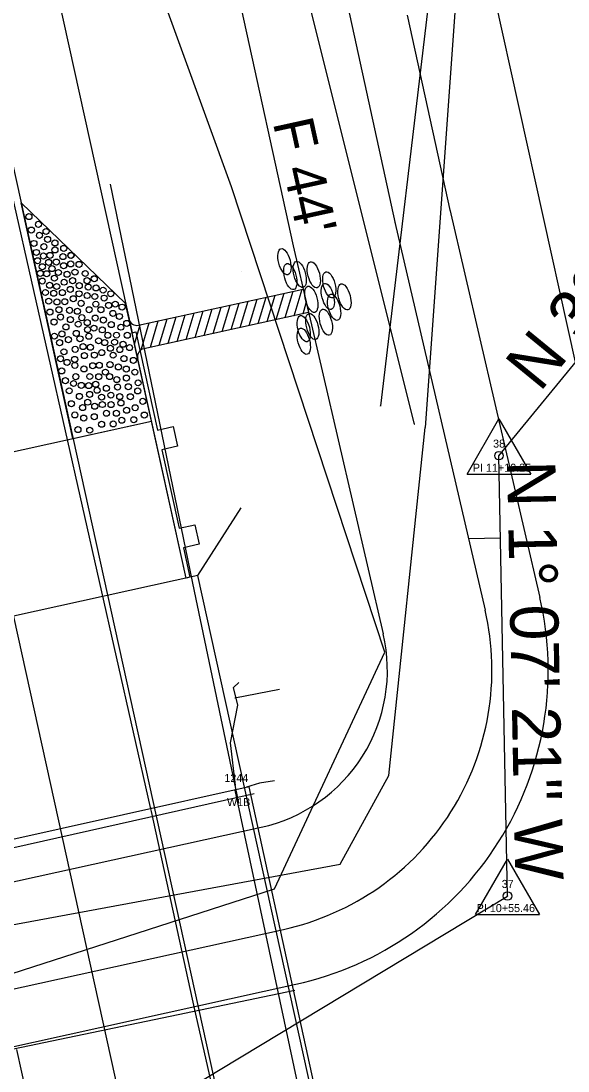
# Model space of a CAD drawing. Extents: x 2519952 to 2531965, y 848341 to 887632.
# Drawn here: x 2524474.1 to 2524542.1, y 869931.6 to 870062.2 of the extents above; entities that cross this region are included whole.
import ezdxf

# ---------------------------------------------------------------- set-up
doc = ezdxf.new("R2010")
doc.units = 0
for name, color, linetype in [('RD_EV_JW', 7, 'Continuous'), ('RD_EX_BldgApp', 7, 'Continuous'), ('RD_EX_BldgApp_txCode', 7, 'Continuous'), ('RD_EX_Bridge', 7, 'Continuous'), ('RD_EX_Conc', 7, 'Continuous'), ('RD_EX_DR_Pipe', 7, 'Continuous'), ('RD_EX_DV_Prop', 7, 'Continuous'), ('RD_EX_GuardRail', 7, 'Continuous'), ('RD_EX_H2O', 7, 'Continuous'), ('RD_EX_Misc', 7, 'Continuous'), ('RD_EX_Road', 7, 'Continuous'), ('RD_EX_RW', 7, 'Continuous'), ('RD_EX_VEG', 7, 'Continuous'), ('RD_HC_Cl', 7, 'Continuous'), ('RD_HC_Data', 7, 'Continuous'), ('RD_HC_Data_Tic', 7, 'Continuous'), ('RD_HC_txCode', 7, 'Continuous'), ('RD_PD_BCA', 7, 'Continuous'), ('RD_PD_Bridge', 7, 'Continuous'), ('RD_PD_CstnLmt', 7, 'Continuous'), ('RD_PD_DR_ErosCtrl', 7, 'Continuous'), ('RD_PD_Final_TrvlWay', 7, 'Continuous'), ('RD_PD_GR', 7, 'Continuous'), ('RD_PD_PaveShd', 7, 'Continuous'), ('RD_PD_TX_CstnLmt', 7, 'Continuous'), ('RD_SMD_Locator', 7, 'Continuous')]:
    doc.layers.add(name, color=color, linetype=linetype)

# ---------------------------------------------------------------- blocks, each defined once
blk = doc.blocks.new('TBC1')
at = {"layer": 'RD_PD_GR'}
blk.add_lwpolyline([(12.5, 2.5), (15, 2.5), (15, 0.49), (25, 0.49), (25, 2.5), (27.5, 2.5), (27.5, 0.49), (31.25, 0.49), (31.25, 0), (0, 0), (0, 0.49), (12.5, 0.49)], close=True, dxfattribs=at)

msp = doc.modelspace()

# ---------------------------------------------------------------- linework, layer by layer
at = {"layer": 'RD_EV_JW'}
msp.add_lwpolyline([(2524458.62, 869939.06), (2524505.66, 869954.24), (2524519.37, 869983.67), (2524500.31, 870041.58), (2524475.26, 870110.59), (2524445.65, 870249.35), (2524428.13, 870321.9), (2524406.09, 870422.33), (2524396.17, 870467.05), (2524425.28, 870470.84), (2524454.75, 870476.78)], dxfattribs=at)
at = {"layer": 'RD_EX_BldgApp'}
msp.add_lwpolyline([(2524516.89, 869892.47), (2524508.77, 869928.99), (2524500.76, 869966.53)], dxfattribs=at)
at = {"layer": 'RD_EX_Bridge'}
for points in [[(2524472.36, 869882.63), (2524518.65, 869892.86), (2524502.52, 869966.92), (2524455.6, 869956.47), (2524472.36, 869882.63)], [(2524505.65, 869967.69), (2524503.79, 869967.38), (2524502.16, 869966.89)]]:
    msp.add_lwpolyline(points, dxfattribs=at)
at = {"layer": 'RD_EX_Conc'}
msp.add_lwpolyline([(2524500.79, 869967.1), (2524500.19, 869972.39), (2524501.1, 869977.08), (2524500.57, 869979.27), (2524501.22, 869979.92)], dxfattribs=at)
at = {"layer": 'RD_EX_DR_Pipe'}
msp.add_line((2524500.72, 869978), (2524506.26, 869979.09), dxfattribs=at)
at = {"layer": 'RD_EX_DV_Prop'}
msp.add_line((2524527.61, 870089.75), (2524592.12, 869796.77), dxfattribs=at)
at = {"layer": 'RD_EX_GuardRail'}
msp.add_lwpolyline([(2524501.24, 869964.94), (2524495.69, 869991.29), (2524485.25, 870041.92)], dxfattribs=at)
at = {"layer": 'RD_EX_H2O'}
for points in [[(2524762.31, 869970.18), (2524733.82, 870018.81), (2524754.68, 870057.75), (2524729.41, 870096.66), (2524680.71, 870131.33), (2524638.06, 870116.86), (2524602.29, 870110.04), (2524572.44, 870077.13), (2524547.77, 870085.27), (2524528.12, 870063.83), (2524524.38, 870011.64)], [(2524436.36, 869952.53), (2524441.15, 869943.87), (2524513.81, 869957.32), (2524519.88, 869968.33), (2524524.38, 870011.64)]]:
    msp.add_lwpolyline(points, dxfattribs=at)
at = {"layer": 'RD_EX_Misc'}
for p, q in [((2524455.91, 869955.49), (2524503.11, 869966.09)), ((2524508.17, 869941.6), (2524461.28, 869931.83))]:
    msp.add_line(p, q, dxfattribs=at)
msp.add_lwpolyline([(2524763.76, 869970.38), (2524734.76, 870019.18), (2524755.4, 870058.09), (2524736.98, 870088.2), (2524730.38, 870097.59), (2524680.98, 870133.01), (2524637.69, 870118.3), (2524601.59, 870111.28), (2524572.31, 870077.7), (2524547.41, 870087.54), (2524525.11, 870066.96), (2524518.84, 870014.31)], dxfattribs=at)
at = {"layer": 'RD_EX_Road'}
for p, q in [((2524490.23, 869964.34), (2524468.69, 870059.82)), ((2524490.35, 869963.86), (2524490.23, 869964.34)), ((2524495.76, 869939.17), (2524490.35, 869963.86)), ((2524501.25, 869914.97), (2524495.76, 869939.17)), ((2524478.97, 869909.8), (2524473.63, 869934.24))]:
    msp.add_line(p, q, dxfattribs=at)
at = {"layer": 'RD_EX_RW'}
msp.add_line((2524527.61, 870089.75), (2524592.12, 869796.77), dxfattribs=at)
at = {"layer": 'RD_EX_VEG'}
msp.add_lwpolyline([(2524523.08, 870012.04), (2524509.32, 870067.13), (2524430.48, 870459.25), (2524384.56, 870681.27)], dxfattribs=at)
at = {"layer": 'RD_HC_Cl'}
for p, q in [((2524338.62, 870599.23), (2524895.21, 868071.59)), ((2524533.56, 870008.13), (2524581.12, 870066.26)), ((2524534.63, 869953.35), (2524533.56, 870008.13)), ((2524369.5, 869853.66), (2524534.63, 869953.35))]:
    msp.add_line(p, q, dxfattribs=at)
at = {"layer": 'RD_HC_Data'}
for p, q in [((2524529.59, 870005.84), (2524533.56, 870012.72)), ((2524533.56, 870012.72), (2524537.53, 870005.84)), ((2524529.59, 870005.84), (2524537.53, 870005.84)), ((2524530.66, 869951.06), (2524534.64, 869957.94)), ((2524534.64, 869957.94), (2524538.6, 869951.06)), ((2524530.66, 869951.06), (2524538.6, 869951.06))]:
    msp.add_line(p, q, dxfattribs=at)
for centre in [(2524533.56, 870008.13), (2524534.63, 869953.35)]:
    msp.add_circle(centre, 0.529, dxfattribs=at)
at = {"layer": 'RD_HC_Data_Tic'}
msp.add_line((2524533.76, 869997.87), (2524529.76, 869997.8), dxfattribs=at)
at = {"layer": 'RD_PD_BCA'}
for p, q in [((2524522.16, 870062.95), (2524527.5, 870038.5)), ((2524527.45, 870038.75), (2524538.66, 869990.48))]:
    msp.add_line(p, q, dxfattribs=at)
msp.add_lwpolyline([(2524459.51, 869931.62), (2524508.29, 869942.37)], dxfattribs=at)
msp.add_arc((2524499.69, 869981.43), 40, 282.4185, 13.0724, dxfattribs=at)
at = {"layer": 'RD_PD_Bridge'}
for p, q in [((2524447.39, 870002.97), (2524490.36, 870012.43)), ((2524494.66, 869992.9), (2524490.36, 870012.43)), ((2524496.13, 869993.22), (2524501.51, 870001.65))]:
    msp.add_line(p, q, dxfattribs=at)
for points in [[(2524496.13, 869993.22), (2524450.23, 869983.12)], [(2524524.08, 869866.26), (2524496.13, 869993.22)]]:
    msp.add_lwpolyline(points, dxfattribs=at)
at = {"layer": 'RD_PD_CstnLmt'}
for p, q in [((2524486.6, 870131.92), (2524507.97, 870034.23)), ((2524507.97, 870034.23), (2524519.17, 869985.96))]:
    msp.add_line(p, q, dxfattribs=at)
msp.add_lwpolyline([(2524455.21, 869951.16), (2524503.99, 869961.9)], dxfattribs=at)
msp.add_arc((2524499.69, 869981.43), 20, 282.4185, 13.0724, dxfattribs=at)
at = {"layer": 'RD_PD_DR_ErosCtrl'}
for p, q in [((2524499.3, 870134.69), (2524520.67, 870037)), ((2524520.63, 870037.17), (2524531.84, 869988.9))]:
    msp.add_line(p, q, dxfattribs=at)
msp.add_lwpolyline([(2524458, 869938.46), (2524506.79, 869949.2)], dxfattribs=at)
msp.add_arc((2524499.69, 869981.43), 33, 282.4185, 13.0724, dxfattribs=at)
at = {"layer": 'RD_PD_Final_TrvlWay'}
msp.add_line((2524439.2, 870198.28), (2524713.39, 868953.11), dxfattribs=at)
at = {"layer": 'RD_PD_GR'}
msp.add_line((2524439.56, 870243.16), (2524487.94, 870023.42), dxfattribs=at)
at = {"layer": 'RD_PD_PaveShd'}
for p, q in [((2524474.14, 870039.58), (2524487.14, 870027.08)), ((2524480.6, 870010.28), (2524474.14, 870039.58)), ((2524488.76, 870024.37), (2524509.21, 870028.86)), ((2524504.74, 870024.81), (2524505.73, 870028.09)), ((2524504.74, 870024.81), (2524505.73, 870028.09)), ((2524505.86, 870025.05), (2524506.84, 870028.34)), ((2524505.86, 870025.05), (2524506.84, 870028.34)), ((2524506.98, 870025.3), (2524507.96, 870028.58)), ((2524506.98, 870025.3), (2524507.84, 870028.18)), ((2524508.09, 870025.54), (2524509.08, 870028.83)), ((2524508.09, 870025.54), (2524509.08, 870028.83)), ((2524509.21, 870028.86), (2524509.89, 870025.94)), ((2524487.78, 870024.15), (2524487.14, 870027.08)), ((2524499.15, 870023.58), (2524500.14, 870026.87)), ((2524499.15, 870023.58), (2524500.14, 870026.87)), ((2524500.27, 870023.82), (2524501.26, 870027.11)), ((2524500.27, 870023.82), (2524501.26, 870027.11)), ((2524501.39, 870024.07), (2524502.37, 870027.36)), ((2524501.39, 870024.07), (2524502.37, 870027.36)), ((2524502.51, 870024.31), (2524503.49, 870027.6)), ((2524502.51, 870024.31), (2524503.49, 870027.6)), ((2524503.62, 870024.56), (2524504.61, 870027.85)), ((2524503.62, 870024.56), (2524504.49, 870027.44)), ((2524509.21, 870025.79), (2524509.61, 870027.13)), ((2524509.21, 870025.79), (2524509.61, 870027.13)), ((2524509.89, 870025.94), (2524489.4, 870021.44)), ((2524493.57, 870022.35), (2524494.55, 870025.64)), ((2524494.69, 870022.6), (2524495.67, 870025.88)), ((2524494.69, 870022.6), (2524495.67, 870025.88)), ((2524495.8, 870022.84), (2524496.79, 870026.13)), ((2524495.8, 870022.84), (2524496.79, 870026.13)), ((2524496.92, 870023.09), (2524497.9, 870026.38)), ((2524496.92, 870023.09), (2524497.9, 870026.38)), ((2524498.04, 870023.33), (2524499.02, 870026.62)), ((2524498.04, 870023.33), (2524499.02, 870026.62)), ((2524488.43, 870021.22), (2524487.78, 870024.15)), ((2524488.25, 870022.02), (2524488.97, 870024.41)), ((2524489.08, 870021.3), (2524490.08, 870024.66)), ((2524490.22, 870021.62), (2524491.2, 870024.9)), ((2524490.22, 870021.62), (2524491.2, 870024.9)), ((2524491.33, 870021.86), (2524492.32, 870025.15)), ((2524491.33, 870021.86), (2524492.32, 870025.15)), ((2524492.45, 870022.11), (2524493.44, 870025.39)), ((2524492.45, 870022.11), (2524493.44, 870025.39)), ((2524490.36, 870012.43), (2524488.43, 870021.22)), ((2524480.6, 870010.28), (2524490.36, 870012.43))]:
    msp.add_line(p, q, dxfattribs=at)
for centre in [(2524475.12, 870037.87), (2524476.31, 870036.91), (2524476.31, 870036.91), (2524475.42, 870036.2), (2524475.42, 870036.2), (2524476.43, 870035.54), (2524476.43, 870035.54), (2524477.25, 870036.02), (2524477.25, 870036.02), (2524475.74, 870034.53), (2524475.74, 870034.53), (2524477.44, 870035.03), (2524477.44, 870035.03), (2524478.36, 870034.6), (2524476.05, 870033.41), (2524476.05, 870033.41), (2524476.93, 870032.97), (2524476.93, 870032.97), (2524476.98, 870034.13), (2524476.98, 870034.13), (2524477.74, 870033.05), (2524477.74, 870033.05), (2524478.36, 870033.72), (2524478.36, 870033.72), (2524479.45, 870033.92), (2524479.45, 870033.92), (2524480.33, 870033.05), (2524480.36, 870033.03), (2524476.19, 870032.38), (2524476.19, 870032.38), (2524476.79, 870031.64), (2524476.79, 870031.64), (2524477.57, 870032.17), (2524477.57, 870032.17), (2524478.53, 870032.22), (2524478.53, 870032.22), (2524479.35, 870032.9), (2524479.35, 870032.9), (2524479.43, 870031.76), (2524479.43, 870031.76), (2524480.32, 870031.98), (2524480.32, 870031.98), (2524481.36, 870031.92), (2524481.36, 870031.92), (2524476.53, 870030.8), (2524476.53, 870030.8), (2524477.33, 870030.77), (2524477.33, 870030.77), (2524477.99, 870031.4), (2524477.99, 870031.4), (2524478.79, 870030.92), (2524478.79, 870030.92), (2524479.86, 870030.7), (2524479.86, 870030.7), (2524480.85, 870030.96), (2524480.85, 870030.96), (2524482.12, 870030.79), (2524482.12, 870030.79), (2524476.77, 870029.85), (2524476.77, 870029.85), (2524477.69, 870029.33), (2524477.69, 870029.33), (2524478.29, 870030.21), (2524478.29, 870030.21), (2524478.57, 870029.18), (2524478.57, 870029.18), (2524479.5, 870029.71), (2524479.5, 870029.71), (2524480.55, 870029.9), (2524480.55, 870029.9), (2524481.38, 870029.28), (2524481.38, 870029.28), (2524482.35, 870029.9), (2524482.35, 870029.9), (2524482.49, 870029.11), (2524482.49, 870029.11), (2524483.24, 870030.14), (2524483.25, 870030.13), (2524483.47, 870029), (2524483.47, 870029), (2524477.18, 870028.43), (2524477.18, 870028.43), (2524478.2, 870028.33), (2524478.2, 870028.33), (2524479.28, 870028.42), (2524479.28, 870028.42), (2524480.26, 870028.82), (2524480.26, 870028.82), (2524481.35, 870028.27), (2524481.35, 870028.27), (2524482.36, 870028.05), (2524482.36, 870028.05), (2524483.31, 870027.93), (2524483.31, 870027.93), (2524484.35, 870028.72), (2524484.35, 870028.72), (2524484.47, 870027.73), (2524484.47, 870027.73), (2524485.3, 870028.27), (2524485.3, 870028.27), (2524477.58, 870027.35), (2524477.58, 870027.35), (2524478.6, 870027.26), (2524478.6, 870027.26), (2524479.58, 870027.28), (2524479.58, 870027.28), (2524480.63, 870027.66), (2524480.63, 870027.66), (2524481.61, 870027.08), (2524481.61, 870027.08), (2524483.44, 870026.98), (2524483.44, 870026.98), (2524485.03, 870026.82), (2524485.03, 870026.82), (2524485.86, 870026.98), (2524485.86, 870026.98), (2524486.7, 870026.61), (2524486.7, 870026.61), (2524486.7, 870026.61), (2524477.73, 870026), (2524477.73, 870026), (2524478.85, 870026.29), (2524478.85, 870026.29), (2524479.05, 870025.37), (2524479.05, 870025.37), (2524480.17, 870026.21), (2524480.17, 870026.21), (2524481.15, 870026.09), (2524481.15, 870026.09), (2524481.7, 870025.3), (2524481.7, 870025.3), (2524482.61, 870026.28), (2524482.61, 870026.28), (2524483.36, 870025.25), (2524483.36, 870025.25), (2524484.08, 870026.28), (2524484.08, 870026.28), (2524485.56, 870025.83), (2524485.56, 870025.83), (2524486.37, 870025.45), (2524486.37, 870025.45), (2524478.25, 870024.75), (2524478.25, 870024.75), (2524479.72, 870024.14), (2524479.72, 870024.14), (2524480.28, 870025.06), (2524480.28, 870025.06), (2524481.25, 870024.49), (2524481.25, 870024.49), (2524482.38, 870024.69), (2524482.38, 870024.69), (2524482.41, 870023.81), (2524482.41, 870023.81), (2524483.21, 870023.99), (2524483.21, 870023.99), (2524484.24, 870023.78), (2524484.24, 870023.78), (2524484.38, 870025), (2524484.38, 870025), (2524485.36, 870024.43), (2524485.36, 870024.43), (2524486.55, 870024.11), (2524486.55, 870024.11), (2524487.28, 870024.58), (2524487.28, 870024.58), (2524478.3, 870023), (2524478.3, 870023), (2524479.23, 870023.28), (2524479.23, 870023.28), (2524480.03, 870022.56), (2524480.03, 870022.56), (2524481.01, 870023.34), (2524481.01, 870023.34), (2524481.47, 870022.67), (2524481.47, 870022.67), (2524482.57, 870022.98), (2524482.57, 870022.98), (2524484.93, 870023.11), (2524484.93, 870023.11), (2524486.01, 870023.12), (2524486.01, 870023.12), (2524487.35, 870023.11), (2524487.35, 870023.11), (2524478.93, 870022.19), (2524478.93, 870022.19), (2524480.87, 870021.36), (2524480.87, 870021.36), (2524481.85, 870021.7), (2524481.85, 870021.7), (2524482.76, 870021.62), (2524482.76, 870021.62), (2524483.79, 870022.42), (2524483.79, 870022.42), (2524484.55, 870022.2), (2524484.55, 870022.2), (2524485.25, 870021.49), (2524485.25, 870021.49), (2524485.77, 870022.25), (2524485.77, 870022.25), (2524486.42, 870021.32), (2524486.42, 870021.32), (2524486.83, 870021.99), (2524486.83, 870021.99), (2524487.63, 870021.57), (2524487.63, 870021.57), (2524479.05, 870020.19), (2524479.47, 870021.05), (2524479.47, 870021.05), (2524480.81, 870020.11), (2524480.81, 870020.11), (2524482.02, 870020.58), (2524482.02, 870020.58), (2524483.26, 870020.64), (2524483.26, 870020.64), (2524484.18, 870020.95), (2524484.18, 870020.95), (2524485.59, 870020.63), (2524485.59, 870020.63), (2524486.93, 870020.2), (2524486.93, 870020.2), (2524488.11, 870019.98), (2524488.11, 870019.98), (2524479.2, 870018.67), (2524479.2, 870018.67), (2524479.86, 870019.73), (2524479.86, 870019.73), (2524480.83, 870019.36), (2524480.83, 870019.36), (2524481.96, 870018.92), (2524481.96, 870018.92), (2524483.05, 870019.32), (2524483.05, 870019.32), (2524483.87, 870019.38), (2524483.87, 870019.38), (2524485.2, 870019.46), (2524485.2, 870019.46), (2524486.25, 870019.17), (2524486.25, 870019.17), (2524487.22, 870018.9), (2524487.22, 870018.9), (2524479.66, 870017.46), (2524479.66, 870017.46), (2524480.95, 870017.96), (2524480.95, 870017.96), (2524482.69, 870017.98), (2524482.69, 870017.98), (2524483.8, 870017.95), (2524483.8, 870017.95), (2524484.63, 870018.52), (2524484.63, 870018.52), (2524485.15, 870017.97), (2524485.15, 870017.97), (2524486.05, 870017.59), (2524486.05, 870017.59), (2524487.24, 870017.79), (2524487.24, 870017.79), (2524488.29, 870018.52), (2524488.29, 870018.52), (2524480.13, 870016.2), (2524480.13, 870016.2), (2524480.67, 870017.11), (2524480.67, 870017.11), (2524481.63, 870016.87), (2524481.63, 870016.87), (2524482.56, 870016.85), (2524482.56, 870016.85), (2524483.43, 870017.01), (2524483.43, 870017.01), (2524483.6, 870016.27), (2524484.75, 870016.51), (2524484.75, 870016.51), (2524486.14, 870016.66), (2524486.14, 870016.66), (2524487.48, 870016.71), (2524487.48, 870016.71), (2524488.65, 870016.18), (2524488.65, 870016.18), (2524488.7, 870017.19), (2524488.7, 870017.19), (2524481.4, 870015.51), (2524481.4, 870015.51), (2524482.43, 870014.78), (2524482.43, 870014.78), (2524482.67, 870015.75), (2524482.67, 870015.75), (2524484.16, 870015.41), (2524484.16, 870015.41), (2524485.31, 870015.66), (2524485.31, 870015.66), (2524486.41, 870015.48), (2524486.41, 870015.48), (2524486.56, 870014.69), (2524486.56, 870014.69), (2524487.73, 870015.46), (2524487.73, 870015.46), (2524489.28, 870014.89), (2524489.28, 870014.89), (2524480.4, 870014.59), (2524480.4, 870014.59), (2524481.8, 870014.11), (2524481.8, 870014.11), (2524483.3, 870014.28), (2524483.3, 870014.28), (2524484.25, 870014.49), (2524484.25, 870014.49), (2524484.76, 870013.41), (2524484.76, 870013.41), (2524485.33, 870014.48), (2524485.33, 870014.48), (2524486, 870013.41), (2524486, 870013.41), (2524487.27, 870013.78), (2524487.27, 870013.78), (2524488.33, 870014.1), (2524488.33, 870014.1), (2524480.83, 870013.2), (2524480.83, 870013.2), (2524481.93, 870012.81), (2524481.93, 870012.81), (2524483.24, 870012.98), (2524483.24, 870012.98), (2524484.16, 870012.04), (2524484.16, 870012.04), (2524485.6, 870012.08), (2524485.6, 870012.08), (2524486.67, 870012.53), (2524486.67, 870012.53), (2524488.16, 870012.6), (2524488.16, 870012.6), (2524489.47, 870013.18), (2524489.47, 870013.18), (2524489.47, 870013.18), (2524481.21, 870011.37), (2524481.21, 870011.37), (2524482.68, 870011.3), (2524482.68, 870011.3)]:
    msp.add_circle(centre, 0.375, dxfattribs=at)
for centre, start, end in [((2524488.54, 870025.34), 192.4185, 282.3889), ((2524489.62, 870020.46), 102.3889, 192.4185)]:
    msp.add_arc(centre, 1, start, end, dxfattribs=at)
for centre in [(2524506.89, 870032.26), (2524507.62, 870030.41), (2524508.79, 870030.68), (2524508.79, 870030.68), (2524510.54, 870030.63), (2524510.54, 870030.63), (2524512.46, 870029.38), (2524512.46, 870029.38), (2524512.28, 870027.94), (2524512.28, 870027.94), (2524514.35, 870027.88), (2524514.35, 870027.88), (2524510.23, 870027.58), (2524510.23, 870027.58), (2524513.07, 870026.59), (2524513.07, 870026.59), (2524509.29, 870023.93), (2524509.29, 870023.93), (2524510.35, 870024.2), (2524510.35, 870024.2), (2524512.04, 870024.73), (2524512.04, 870024.73), (2524509.3, 870022.36), (2524509.3, 870022.36)]:
    msp.add_ellipse(centre, major_axis=(-0.43, 1.62), ratio=0.429445, dxfattribs=at)
at = {"layer": 'RD_SMD_Locator'}
for centre in [(2524485.25, 870041.92), (2524500.31, 870041.58), (2524501.52, 870030.99), (2524518.84, 870014.31), (2524523.08, 870012.04), (2524524.38, 870011.64), (2524524.38, 870011.64), (2524533.56, 870008.13), (2524495.69, 869991.29), (2524519.37, 869983.67), (2524501.22, 869979.92), (2524500.57, 869979.27), (2524506.26, 869979.09), (2524500.72, 869978), (2524501.1, 869977.08), (2524500.19, 869972.39), (2524519.88, 869968.33), (2524500.79, 869967.1), (2524502.16, 869966.89), (2524502.52, 869966.92), (2524503.79, 869967.38), (2524505.65, 869967.69), (2524500.76, 869966.53), (2524503.11, 869966.09), (2524490.23, 869964.34), (2524501.24, 869964.94), (2524490.35, 869963.86), (2524513.81, 869957.32), (2524505.66, 869954.24), (2524534.63, 869953.35), (2524508.17, 869941.6), (2524495.76, 869939.17)]:
    msp.add_circle(centre, 0.001, dxfattribs=at)

# ---------------------------------------------------------------- block references
at = {"layer": 'RD_PD_Bridge', "rotation": -77.58151740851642}
msp.add_blockref('TBC1', (2524487.94, 870023.42), dxfattribs=at)

# ---------------------------------------------------------------- texts
at = {"layer": 'RD_EX_BldgApp_txCode'}
for s, p in [('1244', (2524499.42, 869967.53)), ('W1B', (2524499.75, 869964.53))]:
    msp.add_text(s, height=1, dxfattribs=at).set_placement(p)
at = {"layer": 'RD_HC_Data'}
for s, rotation, p in [('N 39%%d 17\' 08" E', 50.7144, (2524538.65, 870015.93)), ('N 1%%d 07\' 21" W', 271.1226, (2524534.57, 870007.47))]:
    msp.add_text(s, height=6, rotation=rotation, dxfattribs=at).set_placement(p)
at = {"layer": 'RD_HC_txCode'}
for s, p in [('38', (2524532.83, 870009.13)), ('PI 11+10.25', (2524530.31, 870006.13)), ('37', (2524533.9, 869954.35)), ('PI 10+55.46', (2524530.79, 869951.35))]:
    msp.add_text(s, height=1, dxfattribs=at).set_placement(p)
at = {"layer": 'RD_PD_TX_CstnLmt'}
msp.add_text("F 44'", height=5, rotation=282.4185, dxfattribs=at).set_placement((2524505.43, 870049.58))

doc.saveas('drawing.dxf')
